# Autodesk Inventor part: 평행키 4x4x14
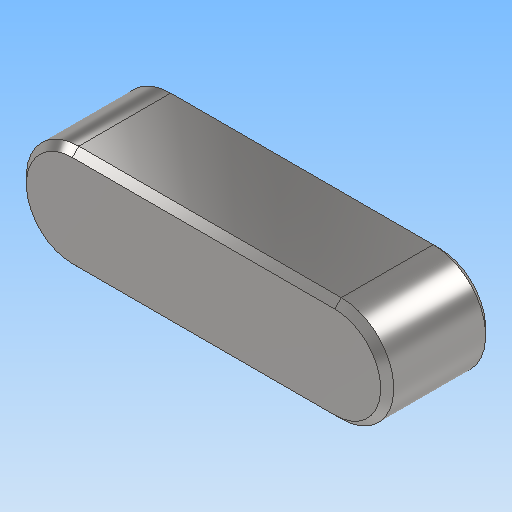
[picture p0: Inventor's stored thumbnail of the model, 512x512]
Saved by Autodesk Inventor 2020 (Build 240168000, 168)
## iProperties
Created: 2024-07
Part Number: 평행키 4x4x14
Material: 강철, 연강
Description: 키 및 해당 키홈
Document SubType Name: Modeling
Designer: oem
Density: 7.85 g/cm^3
Appearance: 기본값
Author: jhkim
Sending System: Autodesk Inventor 2025
Preprocessor: ST-DEVELOPER v20
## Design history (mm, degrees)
feature "Solid1"
node "솔리드1"
